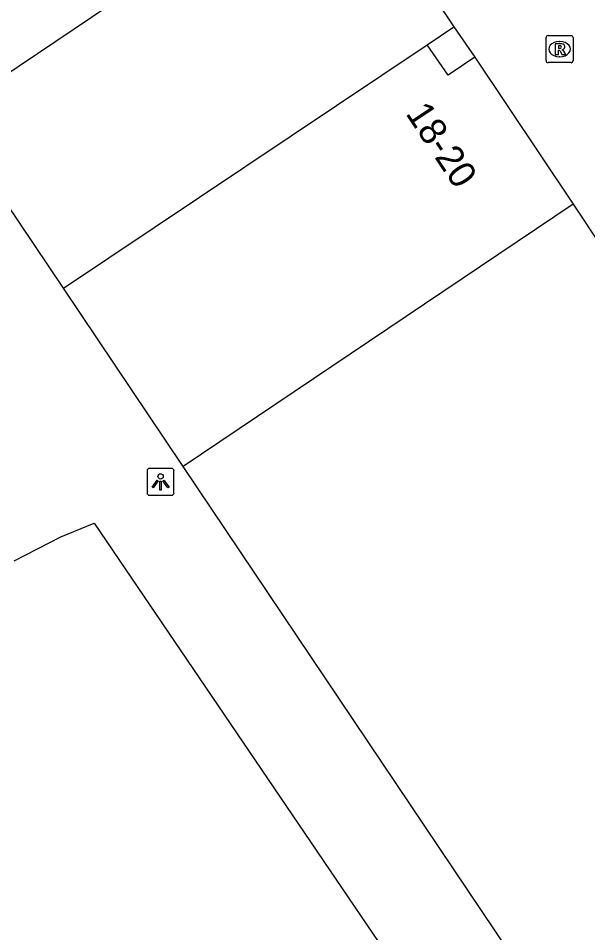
# Model space of a CAD drawing. Extents: x 161087 to 161922, y 382574 to 383873.
# Drawn here: x 161682.36 to 161703.46, y 382955.32 to 382989.18 of the extents above; entities that cross this region are included whole.
import ezdxf

# ---------------------------------------------------------------- set-up
doc = ezdxf.new("R2010")
doc.units = 0
for name, color, linetype in [('IMGEO_Lichtpunt', 7, 'Continuous'), ('IMGEO_Pand', 7, 'Continuous'), ('IMGEO_Pand_nummerreeks', 7, 'Continuous'), ('IMGEO_Rijbaan_lokaal_open', 7, 'Continuous'), ('IMGEO_Rioolput', 7, 'Continuous')]:
    doc.layers.add(name, color=color, linetype=linetype)

msp = doc.modelspace()

# ---------------------------------------------------------------- linework, layer by layer
at = {"layer": 'IMGEO_Lichtpunt'}
for p, q in [((161687.136, 382972.421), (161687.136, 382971.614)), ((161687.136, 382972.421), (161687.136, 382971.614)), ((161688.038, 382972.516), (161687.23, 382972.516)), ((161688.038, 382972.516), (161687.23, 382972.516)), ((161688.132, 382971.614), (161688.132, 382972.421)), ((161688.132, 382971.614), (161688.132, 382972.421)), ((161687.23, 382971.52), (161688.038, 382971.52)), ((161687.23, 382971.52), (161688.038, 382971.52))]:
    msp.add_line(p, q, dxfattribs=at)
for points in [[(161687.51, 382972.085), (161687.549, 382972.057), (161687.361, 382971.795), (161687.323, 382971.822), (161687.51, 382972.085)], [(161687.612, 382972.037), (161687.659, 382972.037), (161687.659, 382971.715), (161687.612, 382971.715), (161687.612, 382972.037)], [(161687.722, 382972.057), (161687.76, 382972.084), (161687.947, 382971.822), (161687.908, 382971.794), (161687.722, 382972.057)]]:
    msp.add_lwpolyline(points, dxfattribs=at)
msp.add_circle((161687.635, 382972.219), 0.0994, dxfattribs=at)
for centre, start, end in [((161687.23, 382972.421), 90, 180), ((161687.23, 382972.421), 90, 180), ((161688.038, 382972.421), 0, 90), ((161688.038, 382972.421), 0, 90), ((161687.23, 382971.614), 180, 270), ((161687.23, 382971.614), 180, 270), ((161688.038, 382971.614), 270, 0), ((161688.038, 382971.614), 270, 360)]:
    msp.add_arc(centre, 0.0946, start, end, dxfattribs=at)
at = {"layer": 'IMGEO_Pand'}
for points in [[(161679.704, 382985.626), (161693.158, 382994.668)], [(161694.925, 382994.203), (161698.499, 382988.867)], [(161697.51, 382988.205), (161698.499, 382988.867)], [(161684.035, 382979.185), (161697.51, 382988.205)], [(161699.272, 382987.742), (161698.284, 382987.079), (161697.51, 382988.205)], [(161699.272, 382987.742), (161702.92, 382982.299)], [(161684.035, 382979.185), (161679.704, 382985.626)], [(161702.92, 382982.299), (161688.472, 382972.585)], [(161702.92, 382982.299), (161704, 382980.687)], [(161688.472, 382972.585), (161684.035, 382979.185)], [(161707.418, 382944.406), (161688.472, 382972.585)], [(161682.205, 382969.111), (161682.211, 382969.099), (161683.938, 382969.979), (161685.174, 382970.483), (161704.677, 382941.781)]]:
    msp.add_lwpolyline(points, dxfattribs=at)
at = {"layer": 'IMGEO_Rijbaan_lokaal_open'}
msp.add_lwpolyline([(161698.499, 382988.867), (161699.272, 382987.742)], dxfattribs=at)
at = {"layer": 'IMGEO_Rioolput'}
for p, q in [((161701.916, 382987.615), (161701.916, 382988.467)), ((161701.991, 382988.541), (161702.843, 382988.541)), ((161702.917, 382988.467), (161702.917, 382987.615)), ((161702.404, 382988.321), (161702.429, 382988.321)), ((161702.843, 382987.541), (161701.991, 382987.541)), ((161702.427, 382987.761), (161702.402, 382987.761))]:
    msp.add_line(p, q, dxfattribs=at)
for points in [[(161701.916, 382987.615), (161701.916, 382988.467)], [(161701.991, 382988.541), (161702.843, 382988.541)], [(161702.917, 382988.467), (161702.917, 382987.615)], [(161702.505, 382988.239), (161702.253, 382988.241), (161702.253, 382987.841)], [(161702.431, 382988.16), (161702.377, 382988.16), (161702.377, 382988.079)], [(161702.253, 382987.841), (161702.377, 382987.841), (161702.377, 382988.003), (161702.388, 382988.003)], [(161702.377, 382988.079), (161702.429, 382988.079)], [(161702.435, 382987.974), (161702.506, 382987.841), (161702.646, 382987.841), (161702.581, 382987.967)], [(161702.843, 382987.541), (161701.991, 382987.541)]]:
    msp.add_lwpolyline(points, dxfattribs=at)
for centre, radius, start, end in [((161701.993, 382988.465), 0.0765, 91.552, 178.448), ((161701.993, 382988.465), 0.0765, 91.552, 178.448), ((161702.841, 382988.465), 0.0765, 1.552, 88.448), ((161702.841, 382988.465), 0.0765, 1.552, 88.448), ((161702.437, 382988.064), 0.0964, 77.0061, 93.1865), ((161702.451, 382988.121), 0.0378, 276.6634, 79.6772), ((161702.504, 382988.129), 0.109, 350.3612, 89.416), ((161702.502, 382988.129), 0.112, 277.5842, 350.9817), ((161702.387, 382987.95), 0.0533, 26.0293, 88.6989), ((161702.413, 382988.268), 0.19, 274.7715, 282.9687), ((161702.486, 382987.914), 0.108, 29.5134, 73.7905), ((161701.993, 382987.617), 0.0765, 181.552, 268.448), ((161701.993, 382987.617), 0.0765, 181.552, 268.448), ((161702.841, 382987.617), 0.0765, 271.552, 358.448), ((161702.841, 382987.617), 0.0765, 271.552, 358.448)]:
    msp.add_arc(centre, radius, start, end, dxfattribs=at)
for centre, major_axis, ratio, start_param, end_param in [((161702.403, 382988.041), (-0.387, 0.002), 0.722429, 4.712389, 7.853982), ((161702.428, 382988.041), (-0.39, 0.002), 0.717154, 1.570796, 4.712389)]:
    msp.add_ellipse(centre, major_axis=major_axis, ratio=ratio, start_param=start_param, end_param=end_param, dxfattribs=at)

# ---------------------------------------------------------------- texts
at = {"layer": 'IMGEO_Pand_nummerreeks'}
msp.add_text('18-20', height=1, rotation=303.658, dxfattribs=at).set_placement((161696.692, 382985.656))

doc.saveas('drawing.dxf')
